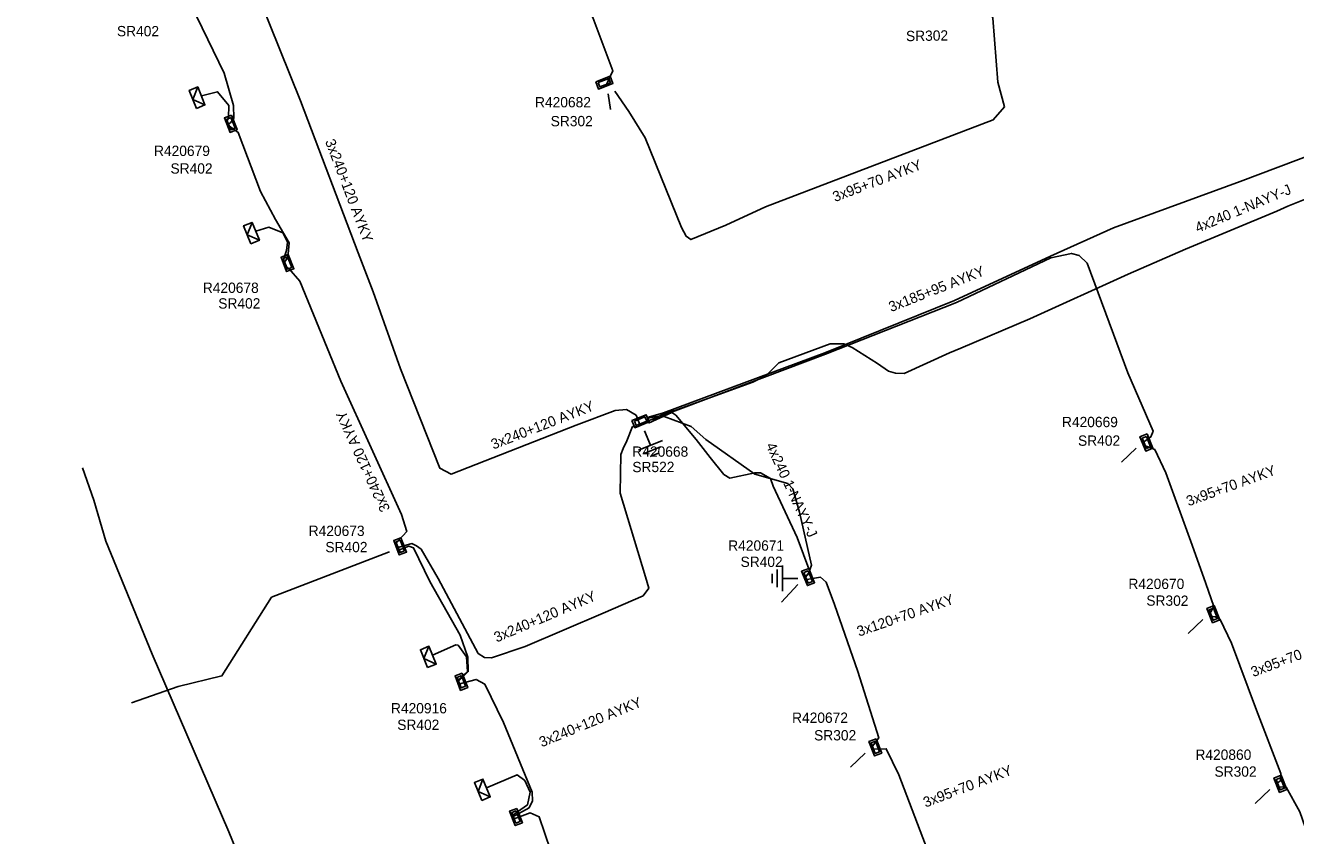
# Model space of a CAD drawing. Extents: x -540028 to -538776, y -1157064 to -1155670.
# Drawn here: x -539941.8 to -539818.5, y -1156414.7 to -1156336.1 of the extents above; entities that cross this region are included whole.
import ezdxf

# ---------------------------------------------------------------- set-up
doc = ezdxf.new("R2010")
doc.units = 0
for name, color, linetype in [('Vrstva 15', 7, 'Continuous'), ('Vrstva 2', 7, 'Continuous'), ('Vrstva 28', 7, 'Continuous'), ('Vrstva 29', 7, 'Continuous'), ('Vrstva 30', 7, 'Continuous'), ('Vrstva 31', 7, 'Continuous'), ('Vrstva 5', 7, 'Continuous'), ('Vrstva 52', 7, 'Continuous'), ('Vrstva 59', 7, 'Continuous'), ('Vrstva 6', 7, 'Continuous'), ('Vrstva 9', 7, 'Continuous')]:
    doc.layers.add(name, color=color, linetype=linetype)

# ---------------------------------------------------------------- blocks, each defined once
blk = doc.blocks.new('132')
at = {"layer": 'Vrstva 2'}
for points in [[(-1.5, 1.5), (1.5, 1.5), (1.5, 0), (-1.5, 0)], [(-1.1, 1.2), (1.1, 1.2), (1.1, 0.3), (-1.1, 0.3)]]:
    blk.add_lwpolyline(points, close=True, dxfattribs=at)
blk = doc.blocks.new('23')
at = {"layer": 'Vrstva 2'}
blk.add_lwpolyline([(1.875, -1.8), (-1.875, -1.8), (-1.875, 0), (1.875, 0)], close=True, dxfattribs=at)
blk.add_lwpolyline([(1.875, 0), (0, -1.8), (-1.875, 0)], dxfattribs=at)
blk = doc.blocks.new('11')
at = {"layer": 'Vrstva 2'}
for p, q in [((0, -4.3), (0, -1.3)), ((-2.5, -4.3), (2.5, -4.3)), ((-1.7, -5.3), (1.7, -5.3)), ((-0.9, -6.3), (0.9, -6.3))]:
    blk.add_line(p, q, dxfattribs=at)

msp = doc.modelspace()

# ---------------------------------------------------------------- linework, layer by layer
at = {"layer": 'Vrstva 5'}
for points in [[(-539941.82, -1156301.44), (-539938.97, -1156300.5), (-539936.79, -1156301.69), (-539930.52, -1156306.05), (-539929.51, -1156307.39), (-539928.75, -1156308.7), (-539928.53, -1156308.99), (-539928.27, -1156309.17), (-539925.64, -1156315.53), (-539922.05, -1156326.09), (-539915.12, -1156343.4), (-539909.49, -1156358.13), (-539908.06, -1156361.94), (-539905.39, -1156369.41), (-539901.58, -1156379.05), (-539900.46, -1156379.61), (-539888.32, -1156374.88), (-539884.55, -1156373.45), (-539883.45, -1156373.33), (-539882.51, -1156373.91), (-539882.12, -1156374.91)], [(-539885.44, -1156341.94), (-539884.76, -1156340.49), (-539886.71, -1156335.29), (-539887.45, -1156334.2), (-539890.38, -1156328.79), (-539890.85, -1156328.17)], [(-539927.53, -1156332.65), (-539926.84, -1156332.76), (-539925.84, -1156333.86), (-539925.16, -1156335.25), (-539922.52, -1156340.69), (-539921.62, -1156343.84), (-539921.58, -1156345.08), (-539921.89, -1156345.51), (-539922.22, -1156345.68)], [(-539851.54, -1156333.08), (-539851.21, -1156332.39), (-539850.06, -1156332.25), (-539849.52, -1156332.63), (-539848.15, -1156334.54), (-539847.87, -1156335.36), (-539847.39, -1156341.57), (-539846.75, -1156343.97), (-539847.83, -1156345.24), (-539869.95, -1156353.67), (-539873.81, -1156355.44), (-539877.19, -1156356.85), (-539877.66, -1156356.53), (-539878.12, -1156355.68), (-539881.63, -1156346.99), (-539883.21, -1156344.42), (-539884.57, -1156342.46)], [(-539922.16, -1156345.83), (-539921.99, -1156345.83), (-539921.15, -1156346.45), (-539918.99, -1156352.18), (-539917.53, -1156354.92), (-539916.19, -1156357.17), (-539916.32, -1156358.58), (-539916.65, -1156359.04), (-539916.74, -1156359.13)], [(-539881.94, -1156374.83), (-539881.83, -1156374.67), (-539879.19, -1156373.5), (-539878.75, -1156373.44), (-539871.17, -1156370.68), (-539869.91, -1156370.07), (-539868.65, -1156368.83), (-539863.68, -1156366.97), (-539862.34, -1156366.97), (-539861.52, -1156367.33), (-539859.08, -1156368.87), (-539858, -1156369.61), (-539857.33, -1156369.81), (-539856.49, -1156369.84), (-539852.07, -1156367.86), (-539850.98, -1156367.4), (-539844.28, -1156364.56), (-539834.73, -1156360.21), (-539829.17, -1156357.8), (-539820.3, -1156354.08), (-539819.22, -1156353.62), (-539812.92, -1156351.09)], [(-539881.5, -1156374.66), (-539881.29, -1156374.14), (-539879.92, -1156373.93), (-539864.13, -1156367.96), (-539851.4, -1156362.95), (-539842.24, -1156358.62), (-539840.25, -1156358.2), (-539839.48, -1156358.4), (-539838.71, -1156359.14), (-539834.75, -1156369.8), (-539832.31, -1156375.44), (-539832.52, -1156376), (-539833.33, -1156376.59)], [(-539916.62, -1156359.46), (-539916.24, -1156359.66), (-539915.16, -1156360.9), (-539911.19, -1156370.6), (-539905.29, -1156383.53), (-539904.78, -1156385.18), (-539905.89, -1156386.4)], [(-539866.16, -1156389.74), (-539865.65, -1156389.07), (-539866.89, -1156385.77), (-539869.19, -1156380.79), (-539869.46, -1156380.03), (-539870.42, -1156379.49), (-539870.99, -1156379.49), (-539873.41, -1156380.01), (-539873.99, -1156379.66), (-539875.31, -1156377.99), (-539876.69, -1156376.27), (-539878.66, -1156373.88), (-539879.05, -1156373.65), (-539881.31, -1156374.66)], [(-539905.75, -1156386.77), (-539904.28, -1156386.36), (-539903.83, -1156386.59), (-539903.38, -1156386.91), (-539901.75, -1156389.74), (-539897.84, -1156397.02), (-539897.24, -1156397.43), (-539896.57, -1156397.46), (-539893.29, -1156396.36), (-539885.7, -1156393.12), (-539881.84, -1156391.44), (-539881.27, -1156390.69), (-539881.59, -1156389.58), (-539884.06, -1156381.48), (-539884, -1156377.73), (-539883.78, -1156377.13), (-539883.41, -1156376.38), (-539882.86, -1156375), (-539882.44, -1156375.03)], [(-539833.24, -1156376.81), (-539832.9, -1156376.94), (-539832.15, -1156377.24), (-539831.06, -1156379.5), (-539828.51, -1156386.51), (-539827.2, -1156390.22), (-539826.4, -1156392.46), (-539826.83, -1156393.22)], [(-539936.27, -1156379.01), (-539935.17, -1156382.16), (-539934, -1156386.11), (-539929.5, -1156397.08), (-539922.06, -1156414.34), (-539911.42, -1156440.51), (-539906.94, -1156451.42), (-539904.12, -1156457.59), (-539903.96, -1156458.69), (-539904.52, -1156459.9), (-539905.72, -1156460.91), (-539915.38, -1156467.98), (-539917.46, -1156469.44)], [(-539931.53, -1156401.82), (-539927, -1156400.24), (-539922.74, -1156399.21), (-539917.92, -1156391.57), (-539906.57, -1156387.18), (-539906.45, -1156387.17)], [(-539905.65, -1156387.02), (-539904.6, -1156386.61), (-539904.13, -1156386.78), (-539902.53, -1156390.03), (-539899.59, -1156395.24), (-539898.86, -1156397.4), (-539898.81, -1156398.79), (-539899.84, -1156399.79)], [(-539866.12, -1156389.88), (-539864.6, -1156389.62), (-539864.06, -1156390.09), (-539863.24, -1156392.28), (-539860.98, -1156398.79), (-539858.95, -1156405.23), (-539859.66, -1156406.14)], [(-539826.76, -1156393.4), (-539826.28, -1156393.46), (-539825.8, -1156393.72), (-539824.71, -1156396.04), (-539822.26, -1156402.54), (-539819.91, -1156408.66), (-539819.95, -1156409.4), (-539820.34, -1156409.66)], [(-539899.77, -1156399.99), (-539898.04, -1156399.54), (-539897.19, -1156400.01), (-539895.38, -1156403.74), (-539892.62, -1156410.48), (-539892.57, -1156411.34), (-539892.9, -1156412), (-539894.55, -1156412.9)], [(-539859.58, -1156406.32), (-539858.22, -1156406.28), (-539857.01, -1156408.79), (-539852.18, -1156421.45), (-539852.7, -1156422.48), (-539853.18, -1156422.63)], [(-539853.12, -1156422.78), (-539851.98, -1156422.96), (-539849.68, -1156426.99), (-539846.07, -1156436.04), (-539845, -1156436.69), (-539844.1, -1156436.81), (-539843.07, -1156436.4), (-539825.27, -1156428.44), (-539815.27, -1156424.04), (-539814.92, -1156422.74), (-539815.01, -1156421.21), (-539815.55, -1156419.63), (-539818.05, -1156412.39), (-539819.4, -1156409.99), (-539820.22, -1156409.98)], [(-539894.46, -1156413.12), (-539892.8, -1156412.5), (-539891.93, -1156412.88), (-539890.82, -1156416.13), (-539887.09, -1156424.1), (-539887.44, -1156425.89), (-539889.25, -1156426.75)]]:
    msp.add_lwpolyline(points, dxfattribs=at)
at = {"layer": 'Vrstva 52'}
for points in [[(-539922.3, -1156345.49), (-539922.09, -1156345.02), (-539922.08, -1156343.83), (-539923.15, -1156342.5), (-539924.73, -1156342.91)], [(-539916.8, -1156358.98), (-539916.78, -1156358.93), (-539916.46, -1156357.92), (-539916.38, -1156357.09), (-539916.82, -1156356.19), (-539918.17, -1156355.66), (-539919.45, -1156356.05)], [(-539899.89, -1156399.68), (-539898.89, -1156398.77), (-539898.99, -1156397.36), (-539899.8, -1156396.23), (-539900.03, -1156396.2), (-539902.28, -1156397.19)], [(-539894.59, -1156412.8), (-539893.07, -1156411.71), (-539892.8, -1156410.5), (-539893.32, -1156409.37), (-539894.05, -1156408.79), (-539897.03, -1156410.08)]]:
    msp.add_lwpolyline(points, dxfattribs=at)
at = {"layer": 'Vrstva 59'}
for points in [[(-539885.24, -1156342.72), (-539885, -1156344.23)], [(-539833.97, -1156377.11), (-539835.39, -1156378.46)], [(-539866.8, -1156390.34), (-539868.39, -1156392.06)], [(-539827.48, -1156393.73), (-539828.9, -1156395.08)], [(-539860.28, -1156406.71), (-539861.69, -1156408.06)], [(-539820.97, -1156410.23), (-539822.39, -1156411.58)]]:
    msp.add_lwpolyline(points, dxfattribs=at)
at = {"layer": 'Vrstva 9'}
for points in [[(-539881.36, -1156374.14), (-539881.31, -1156374.08), (-539879.87, -1156373.66), (-539864.2, -1156367.85), (-539851.61, -1156362.78), (-539842.27, -1156358.46), (-539836.17, -1156355.72), (-539823.87, -1156351.21), (-539798.04, -1156341.48), (-539784.01, -1156336.06), (-539776.7, -1156333.33), (-539773.65, -1156332.23), (-539772.62, -1156333.06), (-539769.74, -1156339.05), (-539769.7, -1156340.03), (-539770.57, -1156340.89), (-539775.43, -1156343.06), (-539778.76, -1156344.53), (-539779.9, -1156345.75), (-539780.25, -1156346.2), (-539780.15, -1156346.77), (-539779.65, -1156347.66)], [(-539881.24, -1156374.44), (-539881.17, -1156374.39), (-539879.8, -1156374.02), (-539877.16, -1156374.98), (-539875.75, -1156376.26), (-539870.99, -1156379.61), (-539867.78, -1156380.52), (-539867.3, -1156381.05), (-539866.64, -1156383.3), (-539865.48, -1156388.46), (-539865.81, -1156389.35), (-539866.25, -1156389.61)]]:
    msp.add_lwpolyline(points, dxfattribs=at)

# ---------------------------------------------------------------- block references
at = {"layer": 'Vrstva 15', "xscale": 0.5, "yscale": 0.5}
for p, rotation in [((-539881.94, -1156374.83), 22.2783838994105), ((-539866.16, -1156389.74), -90)]:
    msp.add_blockref('11', p, dxfattribs=dict(at, rotation=rotation))
at = {"layer": 'Vrstva 28'}
for p, xscale, yscale, rotation in [((-539885.47, -1156341.98), 0.5, 0.5, 21.332450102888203), ((-539922.22, -1156345.75), 0.5, 0.49999999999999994, -68.73398341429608), ((-539916.72, -1156359.26), 0.5, 0.5000000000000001, -68.76888620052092), ((-539881.94, -1156374.83), 0.5, 0.5, 22.2783838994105), ((-539833.31, -1156376.69), 0.5, 0.5, -68.1572111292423), ((-539905.78, -1156386.76), 0.5, 0.5, -68.78244165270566), ((-539866.16, -1156389.74), 0.5, 0.5, -68.21254447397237), ((-539826.81, -1156393.35), 0.49999999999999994, 0.5000000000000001, -68.48378052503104), ((-539899.83, -1156399.91), 0.5, 0.5, -68.75531662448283), ((-539859.63, -1156406.27), 0.5, 0.5, -68.3445222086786), ((-539820.31, -1156409.82), 0.5, 0.5, -68.50490827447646), ((-539894.53, -1156413.03), 0.5, 0.49999999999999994, -68.73398341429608)]:
    msp.add_blockref('132', p, dxfattribs=dict(at, xscale=xscale, yscale=yscale, rotation=rotation))
at = {"layer": 'Vrstva 31', "xscale": 0.49999999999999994, "yscale": 0.5000000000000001}
for p, rotation in [((-539924.73, -1156342.91), -68.08591668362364), ((-539919.45, -1156356.05), -68.08591668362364), ((-539902.28, -1156397.19), -67.81543891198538), ((-539897.03, -1156410.08), -67.81543891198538)]:
    msp.add_blockref('23', p, dxfattribs=dict(at, rotation=rotation))

# ---------------------------------------------------------------- texts
at = {"layer": 'Vrstva 29'}
for s, p in [('R420682', (-539892.33, -1156344.02)), ('R420679', (-539929.33, -1156348.74)), ('R420678', (-539924.59, -1156362.03)), ('R420669', (-539841.16, -1156375.06)), ('R420668', (-539882.88, -1156377.93)), ('R420673', (-539914.31, -1156385.62)), ('R420671', (-539873.57, -1156387.05)), ('R420670', (-539834.71, -1156390.77)), ('R420916', (-539906.32, -1156402.84)), ('R420672', (-539867.37, -1156403.76)), ('R420860', (-539828.2, -1156407.35))]:
    msp.add_text(s, height=1, dxfattribs=at).set_placement(p)
at = {"layer": 'Vrstva 30'}
for s, rotation, p in [('SR402', 359.967, (-539932.93, -1156337.12)), ('SR302', 0.942, (-539856.3, -1156337.6)), ('SR302', 0.131, (-539890.81, -1156345.86)), ('SR402', 359.974, (-539927.73, -1156350.45)), ('SR402', 0.092, (-539923.09, -1156363.55)), ('SR402', 0.142, (-539839.6, -1156376.87)), ('SR522', 0.131, (-539882.88, -1156379.43)), ('SR402', 0.037, (-539912.69, -1156387.2)), ('SR402', 0.03, (-539872.37, -1156388.63)), ('SR302', 359.794, (-539832.97, -1156392.39)), ('SR402', 0.07, (-539905.71, -1156404.45)), ('SR302', 0.105, (-539865.23, -1156405.47)), ('SR302', 0.068, (-539826.35, -1156408.99))]:
    msp.add_text(s, height=1, rotation=rotation, dxfattribs=at).set_placement(p)
at = {"layer": 'Vrstva 6'}
for s, rotation, p in [('3x240+120 AYKY', 290.913, (-539912.74, -1156347.32)), ('3x95+70 AYKY', 20.869, (-539863.2, -1156353.22)), ('4x240 1-NAYY-J', 22.753, (-539827.98, -1156356.21)), ('3x185+95 AYKY', 21.486, (-539857.75, -1156363.9)), ('3x240+120 AYKY', 21.299, (-539896.37, -1156377.24)), ('3x240+120 AYKY', 114.556, (-539906.38, -1156383.01)), ('4x240 1-NAYY-J', 294.79, (-539869.94, -1156376.83)), ('3x95+70 AYKY', 19.935, (-539828.87, -1156382.75)), ('3x240+120 AYKY', 23.083, (-539896.06, -1156395.97)), ('3x120+70 AYKY', 19.126, (-539860.87, -1156395.4)), ('3x95+70 AYKY', 20.634, (-539822.59, -1156399.33)), ('3x240+120 AYKY', 22.251, (-539891.68, -1156406.14)), ('3x95+70 AYKY', 20.86, (-539854.41, -1156411.99))]:
    msp.add_text(s, height=1, rotation=rotation, dxfattribs=at).set_placement(p)

doc.saveas('drawing.dxf')
